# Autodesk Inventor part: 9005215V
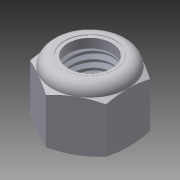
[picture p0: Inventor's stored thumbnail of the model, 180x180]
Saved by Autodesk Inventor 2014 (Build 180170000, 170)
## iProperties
Company: NHTSA/VRTC
Created: 2012-08
Material: Generic
Document SubType Name: Modeling
Designer: Mike Vanvoorhis
Density: 1 g/cm^3
Description: NUT, HEX LOCK 5/8"-11, NYLON-INSERT
Vendor: McMaster Carr
Stock Number: 90630A130
Part Number: 9005215V
Appearance: Default
Translation Standard: IGES 5.3
FileName: C:\SW Working Folder\Fixes\90630A130.igs
PreProcessor: SolidWorks 2007
PostProcessor: Build: 160, Release: 2012 RTM - Date: Tue 03/01/2011
Sent Units: inch
Uncertainty: 1e-08
Author: Dave Walker
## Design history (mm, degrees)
node "90630A130.IGS1"
feature "Composite1"
body "Srf1"
